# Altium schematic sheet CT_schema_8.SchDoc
size 278 x 170 mm
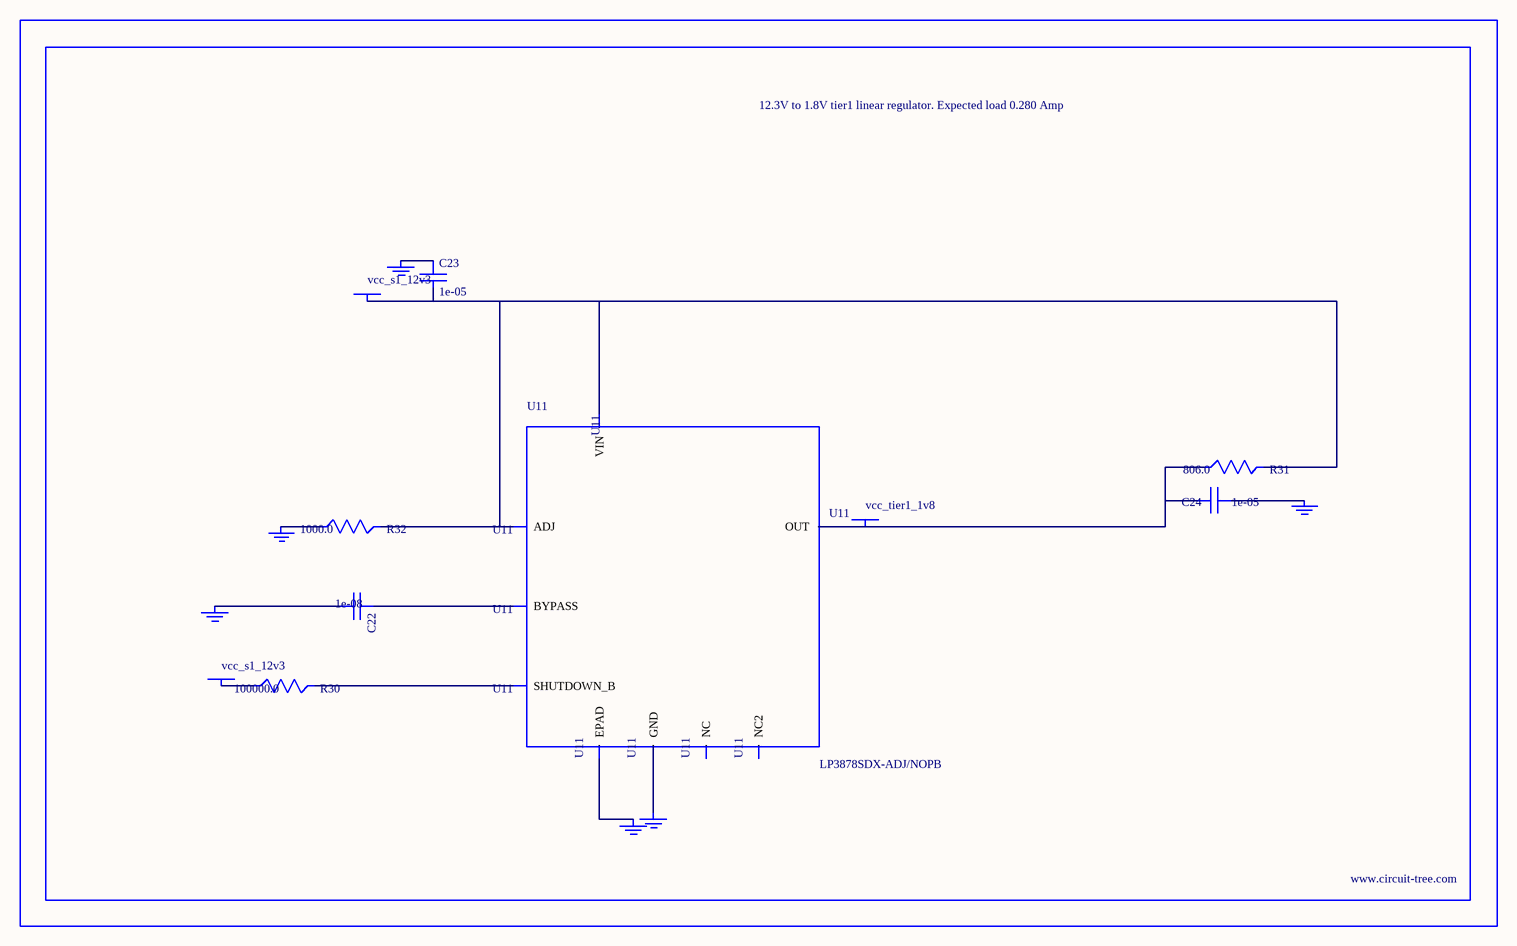
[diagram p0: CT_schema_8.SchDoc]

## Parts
BORDER7  (no value)
C22  1e-08  [C0402]
C23  1e-05  [C1210]
C24  1e-05  [C0805]
GND_INSTANCE_7_0  (no value)
GND_INSTANCE_7_1  (no value)
GND_INSTANCE_7_2  (no value)
GND_INSTANCE_7_3  (no value)
GND_INSTANCE_7_4  (no value)
GND_INSTANCE_7_5  (no value)
POWER_INSTANCE_7_0  vcc_s1_12v3
POWER_INSTANCE_7_1  vcc_s1_12v3
POWER_INSTANCE_7_2  vcc_tier1_1v8
R30  100000.0  [R0603]
R31  806.0  [R0603]
R32  1000.0  [R0603]
U11  LP3878SDX-ADJ/NOPB  [WSON-8]

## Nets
NetC22_1: C22.1 U11.1(BYPASS)
NetC22_2: C22.2 GND_INSTANCE_7_0.0(GND)
NetC23_1: C23.1 GND_INSTANCE_7_1.0(GND)
NetC23_2: C23.2 POWER_INSTANCE_7_0.0(PWR) R31.2 R32.2 U11.4(VIN) U11.6(ADJ)
NetC24_1: C24.1 GND_INSTANCE_7_2.0(GND)
NetC24_2: C24.2 POWER_INSTANCE_7_2.0(PWR) R31.1 U11.5(OUT)
NetGND_INSTANCE_7_3_0: GND_INSTANCE_7_3.0(GND) R32.1
NetGND_INSTANCE_7_4_0: GND_INSTANCE_7_4.0(GND) U11.PAD(EPAD)
NetGND_INSTANCE_7_5_0: GND_INSTANCE_7_5.0(GND) U11.3(GND)
NetPOWER_INSTANCE_7_1_0: POWER_INSTANCE_7_1.0(PWR) R30.1
NetR30_2: R30.2 U11.8(SHUTDOWN_B)

Not connected (* = marked no-connect by the designer): U11 2(NC) 7(NC2)

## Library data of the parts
BORDER7 = BORDER_PAGE7
C22 = C0402C103K3RAC
C23 = C1210C106K5PACTU
C24 = GRM219R60J106ME19D
GND_INSTANCE_7_0-GND_INSTANCE_7_5 = GND
POWER_INSTANCE_7_0-POWER_INSTANCE_7_2 = PWR
R30 = RC0603JR-07100KL
R31 = ERJ-3EKF8060V
R32 = RC0603JR-071KL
